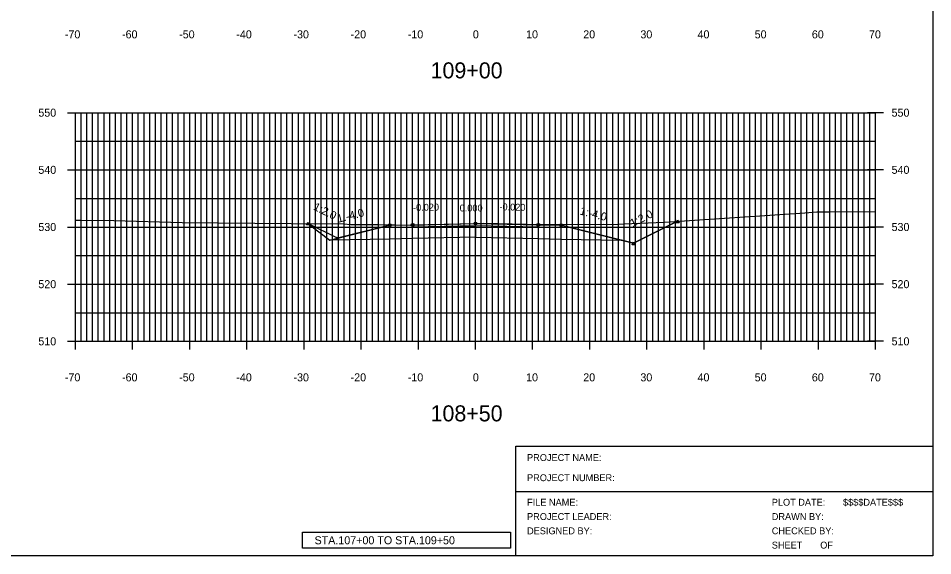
# Model space of a CAD drawing. Extents: x 1509063 to 1512863, y 401160 to 402918.
# Drawn here: x 1512342.7 to 1512502.7, y 402252.1 to 402346.1 of the extents above; entities that cross this region are included whole.
import ezdxf

# ---------------------------------------------------------------- set-up
doc = ezdxf.new("R2010")
doc.units = 0
for name, color, linetype in [('DD_P', 7, 'Continuous'), ('LCUT_P', 7, 'Continuous'), ('NBL1', 7, 'Continuous'), ('PET_P', 7, 'Continuous'), ('PRC', 7, 'Continuous'), ('PSP_P', 7, 'Continuous'), ('RBS_P', 7, 'Continuous'), ('XAX_P', 7, 'Continuous'), ('XAXTIC_P', 7, 'Continuous'), ('XAXTXT_P_T', 7, 'Continuous'), ('XFRAME_P', 7, 'Continuous'), ('XGL_P', 7, 'Continuous'), ('XSL1_P', 7, 'Continuous'), ('XSL1_P_T', 7, 'Continuous'), ('XSL3_P', 7, 'Continuous'), ('XSLOG', 7, 'Continuous')]:
    doc.layers.add(name, color=color, linetype=linetype)

msp = doc.modelspace()

# ---------------------------------------------------------------- linework, layer by layer
at = {"layer": 'DD_P'}
for points in [[(1512458.1, 402310.58), (1512450.4, 402306.73), (1512448.28, 402307.26)], [(1512407.73, 402309.9), (1512398.56, 402307.61), (1512393.39, 402310.19)], [(1512437.73, 402309.9), (1512448.28, 402307.26)]]:
    msp.add_lwpolyline(points, dxfattribs=at)
for points in [[(1512398.56, 402307.86), (1512398.81, 402307.36), (1512398.31, 402307.36)], [(1512450.4, 402306.98), (1512450.65, 402306.48), (1512450.15, 402306.48)]]:
    msp.add_lwpolyline(points, close=True, dxfattribs=at)
at = {"layer": 'LCUT_P'}
for points in [[(1512393.39, 402310.44), (1512393.64, 402309.94), (1512393.14, 402309.94)], [(1512458.1, 402310.83), (1512458.35, 402310.33), (1512457.85, 402310.33)]]:
    msp.add_lwpolyline(points, close=True, dxfattribs=at)
at = {"layer": 'NBL1'}
for p, q in [((1512429.81, 402271.25), (1512502.73, 402271.25)), ((1512429.81, 402252.08), (1512429.81, 402271.25)), ((1512429.81, 402263.33), (1512502.73, 402263.33))]:
    msp.add_line(p, q, dxfattribs=at)
msp.add_lwpolyline([(1512502.73, 402252.08), (1512182.73, 402252.08), (1512182.73, 402462.08), (1512502.73, 402462.08)], close=True, dxfattribs=at)
at = {"layer": 'PET_P'}
for centre in [(1512411.73, 402309.98), (1512433.73, 402309.98)]:
    msp.add_circle(centre, 0.25, dxfattribs=at)
at = {"layer": 'PRC'}
msp.add_circle((1512422.73, 402310.2), 0.25, dxfattribs=at)
at = {"layer": 'PSP_P'}
for centre in [(1512407.73, 402309.9), (1512437.73, 402309.9)]:
    msp.add_circle(centre, 0.25, dxfattribs=at)
at = {"layer": 'RBS_P'}
for points in [[(1512407.8, 402309.48), (1512411.73, 402309.56), (1512422.72, 402309.78), (1512422.72, 402307.78), (1512411.73, 402307.56), (1512407.8, 402307.48), (1512397.22, 402307.27), (1512407.73, 402309.9), (1512407.73, 402309.9)], [(1512422.72, 402309.78), (1512422.72, 402307.78), (1512433.73, 402307.56), (1512437.73, 402307.48), (1512448.24, 402307.27), (1512437.73, 402309.9), (1512437.73, 402309.48), (1512433.73, 402309.56)]]:
    msp.add_lwpolyline(points, close=True, dxfattribs=at)
for points in [[(1512407.73, 402309.9), (1512407.73, 402310.15), (1512407.73, 402309.9), (1512407.48, 402309.9), (1512407.73, 402309.9), (1512407.73, 402309.65), (1512407.73, 402309.9), (1512407.98, 402309.9)], [(1512437.73, 402309.9), (1512437.73, 402310.15), (1512437.73, 402309.9), (1512437.48, 402309.9), (1512437.73, 402309.9), (1512437.73, 402309.65), (1512437.73, 402309.9), (1512437.98, 402309.9)]]:
    msp.add_lwpolyline(points, dxfattribs=at)
at = {"layer": 'XAX_P'}
for p, q in [((1512352.73, 402289.58), (1512352.73, 402329.58)), ((1512422.73, 402289.58), (1512422.73, 402329.58)), ((1512492.73, 402289.58), (1512492.73, 402329.58)), ((1512352.73, 402289.58), (1512492.73, 402289.58))]:
    msp.add_line(p, q, dxfattribs=at)
at = {"layer": 'XAXTIC_P'}
for p, q in [((1512351.33, 402329.58), (1512354.13, 402329.58)), ((1512421.33, 402329.58), (1512424.13, 402329.58)), ((1512494.13, 402329.58), (1512491.33, 402329.58)), ((1512351.33, 402319.58), (1512354.13, 402319.58)), ((1512421.33, 402319.58), (1512424.13, 402319.58)), ((1512494.13, 402319.58), (1512491.33, 402319.58)), ((1512351.33, 402309.58), (1512354.13, 402309.58)), ((1512421.33, 402309.58), (1512424.13, 402309.58)), ((1512494.13, 402309.58), (1512491.33, 402309.58)), ((1512351.33, 402299.58), (1512354.13, 402299.58)), ((1512421.33, 402299.58), (1512424.13, 402299.58)), ((1512494.13, 402299.58), (1512491.33, 402299.58)), ((1512352.73, 402288.18), (1512352.73, 402290.98)), ((1512362.73, 402288.18), (1512362.73, 402290.98)), ((1512372.73, 402288.18), (1512372.73, 402290.98)), ((1512382.73, 402288.18), (1512382.73, 402290.98)), ((1512392.73, 402288.18), (1512392.73, 402290.98)), ((1512402.73, 402288.18), (1512402.73, 402290.98)), ((1512412.73, 402288.18), (1512412.73, 402290.98)), ((1512422.73, 402288.18), (1512422.73, 402290.98)), ((1512432.73, 402288.18), (1512432.73, 402290.98)), ((1512442.73, 402288.18), (1512442.73, 402290.98)), ((1512452.73, 402288.18), (1512452.73, 402290.98)), ((1512462.73, 402288.18), (1512462.73, 402290.98)), ((1512472.73, 402288.18), (1512472.73, 402290.98)), ((1512482.73, 402288.18), (1512482.73, 402290.98)), ((1512492.73, 402288.18), (1512492.73, 402290.98)), ((1512351.33, 402289.58), (1512354.13, 402289.58)), ((1512421.33, 402289.58), (1512424.13, 402289.58)), ((1512494.13, 402289.58), (1512491.33, 402289.58))]:
    msp.add_line(p, q, dxfattribs=at)
at = {"layer": 'XFRAME_P'}
msp.add_lwpolyline([(1512392.43, 402256.18), (1512428.83, 402256.18), (1512428.83, 402253.38), (1512392.43, 402253.38)], close=True, dxfattribs=at)
at = {"layer": 'XGL_P'}
for p, q in [((1512352.73, 402329.58), (1512492.73, 402329.58)), ((1512352.73, 402289.58), (1512352.73, 402329.58)), ((1512353.73, 402289.58), (1512353.73, 402329.58)), ((1512354.73, 402289.58), (1512354.73, 402329.58)), ((1512355.73, 402289.58), (1512355.73, 402329.58)), ((1512356.73, 402289.58), (1512356.73, 402329.58)), ((1512357.73, 402289.58), (1512357.73, 402329.58)), ((1512358.73, 402289.58), (1512358.73, 402329.58)), ((1512359.73, 402289.58), (1512359.73, 402329.58)), ((1512360.73, 402289.58), (1512360.73, 402329.58)), ((1512361.73, 402289.58), (1512361.73, 402329.58)), ((1512362.73, 402289.58), (1512362.73, 402329.58)), ((1512363.73, 402289.58), (1512363.73, 402329.58)), ((1512364.73, 402289.58), (1512364.73, 402329.58)), ((1512365.73, 402289.58), (1512365.73, 402329.58)), ((1512366.73, 402289.58), (1512366.73, 402329.58)), ((1512367.73, 402289.58), (1512367.73, 402329.58)), ((1512368.73, 402289.58), (1512368.73, 402329.58)), ((1512369.73, 402289.58), (1512369.73, 402329.58)), ((1512370.73, 402289.58), (1512370.73, 402329.58)), ((1512371.73, 402289.58), (1512371.73, 402329.58)), ((1512372.73, 402289.58), (1512372.73, 402329.58)), ((1512373.73, 402289.58), (1512373.73, 402329.58)), ((1512374.73, 402289.58), (1512374.73, 402329.58)), ((1512375.73, 402289.58), (1512375.73, 402329.58)), ((1512376.73, 402289.58), (1512376.73, 402329.58)), ((1512377.73, 402289.58), (1512377.73, 402329.58)), ((1512378.73, 402289.58), (1512378.73, 402329.58)), ((1512379.73, 402289.58), (1512379.73, 402329.58)), ((1512380.73, 402289.58), (1512380.73, 402329.58)), ((1512381.73, 402289.58), (1512381.73, 402329.58)), ((1512382.73, 402289.58), (1512382.73, 402329.58)), ((1512383.73, 402289.58), (1512383.73, 402329.58)), ((1512384.73, 402289.58), (1512384.73, 402329.58)), ((1512385.73, 402289.58), (1512385.73, 402329.58)), ((1512386.73, 402289.58), (1512386.73, 402329.58)), ((1512387.73, 402289.58), (1512387.73, 402329.58)), ((1512388.73, 402289.58), (1512388.73, 402329.58)), ((1512389.73, 402289.58), (1512389.73, 402329.58)), ((1512390.73, 402289.58), (1512390.73, 402329.58)), ((1512391.73, 402289.58), (1512391.73, 402329.58)), ((1512392.73, 402289.58), (1512392.73, 402329.58)), ((1512393.73, 402289.58), (1512393.73, 402329.58)), ((1512394.73, 402289.58), (1512394.73, 402329.58)), ((1512395.73, 402289.58), (1512395.73, 402329.58)), ((1512396.73, 402289.58), (1512396.73, 402329.58)), ((1512397.73, 402289.58), (1512397.73, 402329.58)), ((1512398.73, 402289.58), (1512398.73, 402329.58)), ((1512399.73, 402289.58), (1512399.73, 402329.58)), ((1512400.73, 402289.58), (1512400.73, 402329.58)), ((1512401.73, 402289.58), (1512401.73, 402329.58)), ((1512402.73, 402289.58), (1512402.73, 402329.58)), ((1512403.73, 402289.58), (1512403.73, 402329.58)), ((1512404.73, 402289.58), (1512404.73, 402329.58)), ((1512405.73, 402289.58), (1512405.73, 402329.58)), ((1512406.73, 402289.58), (1512406.73, 402329.58)), ((1512407.73, 402289.58), (1512407.73, 402329.58)), ((1512408.73, 402289.58), (1512408.73, 402329.58)), ((1512409.73, 402289.58), (1512409.73, 402329.58)), ((1512410.73, 402289.58), (1512410.73, 402329.58)), ((1512411.73, 402289.58), (1512411.73, 402329.58)), ((1512412.73, 402289.58), (1512412.73, 402329.58)), ((1512413.73, 402289.58), (1512413.73, 402329.58)), ((1512414.73, 402289.58), (1512414.73, 402329.58)), ((1512415.73, 402289.58), (1512415.73, 402329.58)), ((1512416.73, 402289.58), (1512416.73, 402329.58)), ((1512417.73, 402289.58), (1512417.73, 402329.58)), ((1512418.73, 402289.58), (1512418.73, 402329.58)), ((1512419.73, 402289.58), (1512419.73, 402329.58)), ((1512420.73, 402289.58), (1512420.73, 402329.58)), ((1512421.73, 402289.58), (1512421.73, 402329.58)), ((1512422.73, 402289.58), (1512422.73, 402329.58)), ((1512423.73, 402289.58), (1512423.73, 402329.58)), ((1512424.73, 402289.58), (1512424.73, 402329.58)), ((1512425.73, 402289.58), (1512425.73, 402329.58)), ((1512426.73, 402289.58), (1512426.73, 402329.58)), ((1512427.73, 402289.58), (1512427.73, 402329.58)), ((1512428.73, 402289.58), (1512428.73, 402329.58)), ((1512429.73, 402289.58), (1512429.73, 402329.58)), ((1512430.73, 402289.58), (1512430.73, 402329.58)), ((1512431.73, 402289.58), (1512431.73, 402329.58)), ((1512432.73, 402289.58), (1512432.73, 402329.58)), ((1512433.73, 402289.58), (1512433.73, 402329.58)), ((1512434.73, 402289.58), (1512434.73, 402329.58)), ((1512435.73, 402289.58), (1512435.73, 402329.58)), ((1512436.73, 402289.58), (1512436.73, 402329.58)), ((1512437.73, 402289.58), (1512437.73, 402329.58)), ((1512438.73, 402289.58), (1512438.73, 402329.58)), ((1512439.73, 402289.58), (1512439.73, 402329.58)), ((1512440.73, 402289.58), (1512440.73, 402329.58)), ((1512441.73, 402289.58), (1512441.73, 402329.58)), ((1512442.73, 402289.58), (1512442.73, 402329.58)), ((1512443.73, 402289.58), (1512443.73, 402329.58)), ((1512444.73, 402289.58), (1512444.73, 402329.58)), ((1512445.73, 402289.58), (1512445.73, 402329.58)), ((1512446.73, 402289.58), (1512446.73, 402329.58)), ((1512447.73, 402289.58), (1512447.73, 402329.58)), ((1512448.73, 402289.58), (1512448.73, 402329.58)), ((1512449.73, 402289.58), (1512449.73, 402329.58)), ((1512450.73, 402289.58), (1512450.73, 402329.58)), ((1512451.73, 402289.58), (1512451.73, 402329.58)), ((1512452.73, 402289.58), (1512452.73, 402329.58)), ((1512453.73, 402289.58), (1512453.73, 402329.58)), ((1512454.73, 402289.58), (1512454.73, 402329.58)), ((1512455.73, 402289.58), (1512455.73, 402329.58)), ((1512456.73, 402289.58), (1512456.73, 402329.58)), ((1512457.73, 402289.58), (1512457.73, 402329.58)), ((1512458.73, 402289.58), (1512458.73, 402329.58)), ((1512459.73, 402289.58), (1512459.73, 402329.58)), ((1512460.73, 402289.58), (1512460.73, 402329.58)), ((1512461.73, 402289.58), (1512461.73, 402329.58)), ((1512462.73, 402289.58), (1512462.73, 402329.58)), ((1512463.73, 402289.58), (1512463.73, 402329.58)), ((1512464.73, 402289.58), (1512464.73, 402329.58)), ((1512465.73, 402289.58), (1512465.73, 402329.58)), ((1512466.73, 402289.58), (1512466.73, 402329.58)), ((1512467.73, 402289.58), (1512467.73, 402329.58)), ((1512468.73, 402289.58), (1512468.73, 402329.58)), ((1512469.73, 402289.58), (1512469.73, 402329.58)), ((1512470.73, 402289.58), (1512470.73, 402329.58)), ((1512471.73, 402289.58), (1512471.73, 402329.58)), ((1512472.73, 402289.58), (1512472.73, 402329.58)), ((1512473.73, 402289.58), (1512473.73, 402329.58)), ((1512474.73, 402289.58), (1512474.73, 402329.58)), ((1512475.73, 402289.58), (1512475.73, 402329.58)), ((1512476.73, 402289.58), (1512476.73, 402329.58)), ((1512477.73, 402289.58), (1512477.73, 402329.58)), ((1512478.73, 402289.58), (1512478.73, 402329.58)), ((1512479.73, 402289.58), (1512479.73, 402329.58)), ((1512480.73, 402289.58), (1512480.73, 402329.58)), ((1512481.73, 402289.58), (1512481.73, 402329.58)), ((1512482.73, 402289.58), (1512482.73, 402329.58)), ((1512483.73, 402289.58), (1512483.73, 402329.58)), ((1512484.73, 402289.58), (1512484.73, 402329.58)), ((1512485.73, 402289.58), (1512485.73, 402329.58)), ((1512486.73, 402289.58), (1512486.73, 402329.58)), ((1512487.73, 402289.58), (1512487.73, 402329.58)), ((1512488.73, 402289.58), (1512488.73, 402329.58)), ((1512489.73, 402289.58), (1512489.73, 402329.58)), ((1512490.73, 402289.58), (1512490.73, 402329.58)), ((1512491.73, 402289.58), (1512491.73, 402329.58)), ((1512492.73, 402289.58), (1512492.73, 402329.58)), ((1512352.73, 402324.58), (1512492.73, 402324.58)), ((1512352.73, 402319.58), (1512492.73, 402319.58)), ((1512352.73, 402314.58), (1512492.73, 402314.58)), ((1512352.73, 402309.58), (1512492.73, 402309.58)), ((1512352.73, 402304.58), (1512492.73, 402304.58)), ((1512352.73, 402299.58), (1512492.73, 402299.58)), ((1512352.73, 402294.58), (1512492.73, 402294.58)), ((1512352.73, 402289.58), (1512492.73, 402289.58))]:
    msp.add_line(p, q, dxfattribs=at)
at = {"layer": 'XSL1_P'}
msp.add_lwpolyline([(1512393.39, 402310.19), (1512397.22, 402307.27), (1512398.56, 402307.61), (1512407.73, 402309.9), (1512411.73, 402309.98), (1512422.73, 402310.2), (1512433.73, 402309.98), (1512437.73, 402309.9), (1512448.24, 402307.27), (1512448.28, 402307.26), (1512450.4, 402306.73), (1512458.1, 402310.58)], dxfattribs=at)
at = {"layer": 'XSL3_P'}
msp.add_lwpolyline([(1512411.73, 402309.56), (1512407.8, 402309.48), (1512407.73, 402309.9), (1512411.73, 402309.98), (1512422.72, 402310.2), (1512433.73, 402309.98), (1512437.73, 402309.9), (1512437.73, 402309.48), (1512433.73, 402309.56), (1512422.72, 402309.78)], close=True, dxfattribs=at)
at = {"layer": 'XSLOG'}
msp.add_lwpolyline([(1512352.73, 402310.78), (1512353.63, 402310.79), (1512359.47, 402310.74), (1512371.38, 402310.39), (1512390.5, 402310.21), (1512399.65, 402310.15), (1512400.99, 402310.02), (1512405.73, 402310.04), (1512408.69, 402309.97), (1512411.38, 402309.91), (1512422.43, 402310.21), (1512424.2, 402310.26), (1512434.16, 402310.02), (1512435.64, 402309.99), (1512445.09, 402310.05), (1512446.89, 402310.03), (1512447.68, 402310.05), (1512448.6, 402310.12), (1512455.79, 402310.42), (1512480.36, 402312.08), (1512482.47, 402312.23), (1512484.81, 402312.25), (1512492.73, 402312.27)], dxfattribs=at)

# ---------------------------------------------------------------- texts
at = {"layer": 'NBL1'}
for s, p in [('PROJECT NAME:', (1512431.75, 402268.65)), ('PROJECT NUMBER:', (1512431.75, 402265.12)), ('FILE NAME:', (1512431.75, 402260.83)), ('PLOT DATE:', (1512474.57, 402260.83)), ('$$$$DATE$$$', (1512487.03, 402260.83)), ('PROJECT LEADER:', (1512431.75, 402258.33)), ('DRAWN BY:', (1512474.57, 402258.33)), ('DESIGNED BY:', (1512431.75, 402255.83)), ('CHECKED BY:', (1512474.57, 402255.83)), ('SHEET       OF', (1512474.57, 402253.33))]:
    msp.add_text(s, height=1.2, rotation=360, dxfattribs=at).set_placement(p)
at = {"layer": 'XAXTXT_P_T'}
for s, height, p in [('-70', 1.4, (1512350.88, 402342.58)), ('-60', 1.4, (1512360.88, 402342.58)), ('-50', 1.4, (1512370.88, 402342.58)), ('-40', 1.4, (1512380.88, 402342.58)), ('-30', 1.4, (1512390.88, 402342.58)), ('-20', 1.4, (1512400.88, 402342.58)), ('-10', 1.4, (1512410.88, 402342.58)), ('0', 1.4, (1512422.27, 402342.58)), ('10', 1.4, (1512431.58, 402342.58)), ('20', 1.4, (1512441.58, 402342.58)), ('30', 1.4, (1512451.58, 402342.58)), ('40', 1.4, (1512461.58, 402342.58)), ('50', 1.4, (1512471.58, 402342.58)), ('60', 1.4, (1512481.58, 402342.58)), ('70', 1.4, (1512491.58, 402342.58)), ('109+00', 2.8, (1512414.87, 402335.58)), ('550', 1.4, (1512346.24, 402328.88)), ('550', 1.4, (1512495.53, 402328.88)), ('540', 1.4, (1512346.24, 402318.88)), ('540', 1.4, (1512495.53, 402318.88)), ('530', 1.4, (1512346.24, 402308.88)), ('530', 1.4, (1512495.53, 402308.88)), ('520', 1.4, (1512346.24, 402298.88)), ('520', 1.4, (1512495.53, 402298.88)), ('510', 1.4, (1512346.24, 402288.88)), ('510', 1.4, (1512495.53, 402288.88)), ('-70', 1.4, (1512350.88, 402282.58)), ('-60', 1.4, (1512360.88, 402282.58)), ('-50', 1.4, (1512370.88, 402282.58)), ('-40', 1.4, (1512380.88, 402282.58)), ('-30', 1.4, (1512390.88, 402282.58)), ('-20', 1.4, (1512400.88, 402282.58)), ('-10', 1.4, (1512410.88, 402282.58)), ('0', 1.4, (1512422.27, 402282.58)), ('10', 1.4, (1512431.58, 402282.58)), ('20', 1.4, (1512441.58, 402282.58)), ('30', 1.4, (1512451.58, 402282.58)), ('40', 1.4, (1512461.58, 402282.58)), ('50', 1.4, (1512471.58, 402282.58)), ('60', 1.4, (1512481.58, 402282.58)), ('70', 1.4, (1512491.58, 402282.58)), ('108+50', 2.8, (1512414.87, 402275.58))]:
    msp.add_text(s, height=height, dxfattribs=at).set_placement(p)
at = {"layer": 'XFRAME_P'}
msp.add_text('STA.107+00 TO STA.109+50', height=1.4, dxfattribs=at).set_placement((1512394.57, 402254.08))
at = {"layer": 'XSL1_P_T'}
for s, height, rotation, p in [('1:2.0', 1.4, 333.4349, (1512394.24, 402312.67)), ('1:2.0', 1.4, 333.4349, (1512394.24, 402312.67)), ('1:2.0', 1.4, 333.4349, (1512394.24, 402312.67)), ('-0.020', 1.2, 1.142, (1512411.81, 402312.38)), ('-0.020', 1.2, 358.8542, (1512426.91, 402312.51)), ('1:-4.0', 1.4, 14.0362, (1512398.7, 402310.32)), ('1:-4.0', 1.4, 14.0362, (1512398.7, 402310.32)), ('1:-4.0', 1.4, 14.0362, (1512398.7, 402310.32)), ('0.000', 1.2, 359.9981, (1512419.96, 402312.3)), ('0.000', 1.2, 359.9981, (1512419.96, 402312.3)), ('1:-4.0', 1.4, 345.9638, (1512440.88, 402311.79)), ('1:-4.0', 1.4, 345.9638, (1512440.88, 402311.79)), ('1:-4.0', 1.4, 345.9638, (1512440.88, 402311.79)), ('1:2.0', 1.4, 26.5651, (1512450.2, 402309.53)), ('1:2.0', 1.4, 26.5651, (1512450.2, 402309.53)), ('1:2.0', 1.4, 26.5651, (1512450.2, 402309.53))]:
    msp.add_text(s, height=height, rotation=rotation, dxfattribs=at).set_placement(p)

doc.saveas('drawing.dxf')
